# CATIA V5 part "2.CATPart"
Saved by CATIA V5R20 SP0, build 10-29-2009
Part number: 2
Bounding box of the stored display mesh (mm): x -16.36 to 16.358, y -39.957 to 126.41, z -10.705 to 9.852
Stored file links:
  E:\Ehsan\Amoozesh\CATIA\CATIA Course\Advanced\Videos\Session-23\2.CATPart
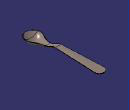
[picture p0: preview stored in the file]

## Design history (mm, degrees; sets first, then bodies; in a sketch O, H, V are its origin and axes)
AxisSystem1: origin (0, 0, 0), X (1, 0, 0), Y (0, 1, 0), Z (0, 0, 1)
Set1
  Plane1: type Offset, RefPlane XY plane of AxisSystem1, Offset 8
  Sketch1 on Plane1, origin (0, 0, 8), H (0, 1, 0), V (-1, 0, 0)
    point P1 (30, 6)
    line L1 (30, 6) -> (117, 9.9796)
    point P2 (117, 9.9796)
    arc A1 centre (117.4112, 0.989) radius 9 from (117, 9.9796) to (126.3567, 0) cw
    point P4 (126.3567, 0)
    distance P2 V = 117
    distance P1 V = 30
    angle L1 H = 2.619
    radius A1 = 9
    distance P1 H = 6
    coincidence: P4 H
    tangency: A1 L1
  Curve1: Elements the part
  Join1: Elements (Sketch1; Curve1; Sketch5)
  Symmetry1: ToTransfor Join1, Reference YZ plane of AxisSystem1
  Plane2: type Offset, RefPlane ZX plane of AxisSystem1, Offset 30, reversed
  Plane3: type Offset, RefPlane ZX plane of AxisSystem1, Offset 15, reversed
  Plane4: type Normal, Curve Join1, RefPoint vertex [face of Curve1 | element of Sketch1]
  Intersect1: ToIntersect1 Plane2, ToIntersect2 Symmetry1
  Intersect2: ToIntersect1 Plane2, ToIntersect2 Join1
  Intersect3: ToIntersect1 Plane3, ToIntersect2 Symmetry1
  Intersect4: ToIntersect1 Plane3, ToIntersect2 Join1
  Sketch2 on Plane2, origin (0, -30, 0), H (-1, 0, 0), V (0, 0, 1)
    spline S1 through (15.1306, 0) (10, -5) (0, -7.5) (-10, -5) (-15.1306, 0)
    reference projected point E1 (15.1306, 0) from Intersect2
    reference projected point E2 (-15.1306, 0) from Intersect1
    point P1 (0, -7.5)
    point P2 (15.1306, 0)
    point P3 (-15.1306, 0)
    coincidence: P1 V, P2 E1, P3 E2
  Sketch3 on Plane3, origin (0, -15, 0), H (-1, 0, 0), V (0, 0, 1)
    spline S1 through (13.8617, 0) (9.7533, -6.3207) (0, -9.6546) (-9.0453, -6.9557) (-13.8617, 0)
    reference projected point E1 (-13.8617, 0) from Intersect3
    reference projected point E2 (13.8617, 0) from Intersect4
    point P1 (0, -9.6546)
    point P2 (-13.8617, 0)
    point P3 (13.8617, 0)
    coincidence: P1 V, P2 E1, P3 E2
  Plane5: type OffsetPt, RefPlane ZX plane of AxisSystem1, RefPoint vertex [face of Symmetry1 | face of Symmetry1]
  Sketch4 on Plane5, origin (0, 5.537, 0), H (-1, 0, 0), V (0, 0, 1)
    spline S1 through (-5.963, 0) (-2.5603, -2.5982) (2.9569, -2.5116) (5.963, 0)
    reference projected point E1 (5.963, 0) from vertex [element of Sketch5 | face of Curve1]
    reference projected point E2 (-5.963, 0) from vertex [face of Symmetry1 | face of Symmetry1]
    point P1 (5.963, 0)
    point P2 (-5.963, 0)
    coincidence: P1 E1, P2 E2
  Curve2: Elements the part
  Loft1: Sections (Sketch2; Sketch3; Sketch4; Curve2), Guides (Join1; Symmetry1)
  Split1: ToCut Join1, Cutting Sketch2
  Split2: ToCut Symmetry1, Cutting Sketch2
  Fill1: Boundary ({fillboundary BoundaryWire Sketch2, Support Loft1}; Split1; Split2)
  Fill2: Boundary ({split ToCut Join1, Cutting Sketch2}; {split ToCut Symmetry1, Cutting Sketch2}; {fillboundary BoundaryWire Curve2, Support Loft1})
  Join2: Elements (Fill2; Loft1; Fill1)
  ThickSurface1: Surface Join2, TopOffset 1, BotOffset 0
  Fillet1: radius 0.1, on face of ThickSurface1
  Fillet2: radius 0.1, on face of ThickSurface1
Body1 (main body)
  Sketch5 on XY plane of AxisSystem1, origin (0, 0, 0), H (0, 1, 0), V (-1, 0, 0)
    spline S1 through (5.537, 5.963) (-11.46, 11.993) (-25, 16.37) (-35.428, 11.365) (-40, 0)
    reference projected line E1 through (0, 0) direction (0, -1) from edge [XY plane of AxisSystem1 | ZX plane of AxisSystem1]
    point P1 (-40, 0)
    point P2 (-35.428, 11.365)
    point P3 (-25, 16.37)
    point P4 (-11.46, 11.993)
    point P5 (5.537, 5.963)
    distance P1 E1 = 40
    distance V P2 = 35.428
    distance P3 V = 25
    distance P4 V = 11.46
    distance P5 V = 5.537
    distance P2 H = 11.365
    distance H P3 = 16.37
    distance P4 H = 11.993
    distance P5 H = 5.963
    coincidence: P1 H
